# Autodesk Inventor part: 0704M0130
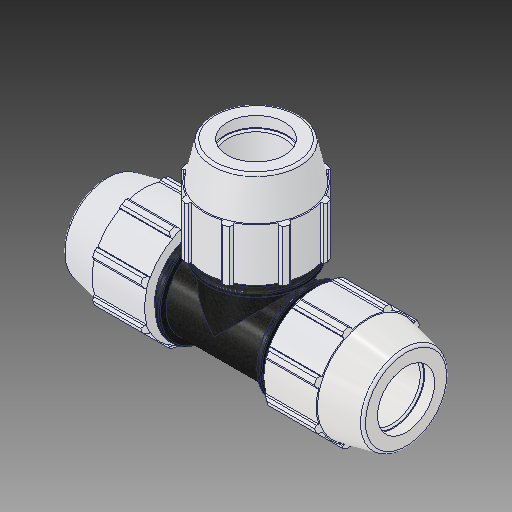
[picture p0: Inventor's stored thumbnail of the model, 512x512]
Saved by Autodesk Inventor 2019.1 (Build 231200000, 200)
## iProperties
Created: 2017-02
Part Number: 0704M0130
Material: PVC-Piping
Description: PLASSON TEE 1 1/4'' - 1 1/4'' - 1 1/4''
Document SubType Name: Modeling
Designer: KIM
Mass: 92.6774 g
Surface Area: 199.44 cm^2
Volume: 66.1981 cm^3
Density: 1.4 g/cm^3
Appearance: PTFE
Author: KIM
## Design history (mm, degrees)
derived "0704M0.ipt"
feature "Solid1::0704M0.ipt"
tag "TaggingFeature1"
body "Solid1"
other parameters: "d_" = 42.1, "E_" = 82.042, "A_" = 110.998, "l_" = 86.106, "H_" = 220.98, "d2" = 42.1, "d4" = 9.24983, "d5" = 27.7495, "d7" = 82.042, "d11" = 3.69993, "d13" = 120 deg, "d14" = 63.15, "d15" = 12 deg, "d16" = 71.37654, "d18" = 2.105, "d19" = 35 deg, "d20" = 17.5 deg, "d21" = 76.29906, "d23" = 0, "d25" = 360 deg, "d27" = 1.64084, "d33" = 0.842, "d42" = 38.8493, "d43" = 2.46126, "d46" = 1.263, "d63" = 86.106, "d67" = 61.5315, "d76" = 42.1, "d77" = 82.042, "d78" = 12 deg, "d79" = 110.998, "d80" = 120 deg, "d81" = 63.15, "d82" = 9.24983, "d85" = 61.5315, "d86" = 71.37654, "d87" = 3.69993, "d88" = 3.69993, "d89" = 27.7495, "d90" = 38.8493, "d96" = 11.0998, "d98" = 76.29906, "d99" = 35 deg, "d100" = 17.5 deg, "d102" = 0, "d103" = 1.64084, "d107" = 360 deg, "d109" = 1.263, "d112" = 2.105, "d118" = 360 deg, "d121" = 0, "d128" = 220.98, "d131" = 37.89, "d132" = 37.89, "d133" = 86.106, "d134" = 1.72212, "d135" = 11.0998, "d152" = 0, "d154" = 0, "d156" = 0, "d158" = 0
